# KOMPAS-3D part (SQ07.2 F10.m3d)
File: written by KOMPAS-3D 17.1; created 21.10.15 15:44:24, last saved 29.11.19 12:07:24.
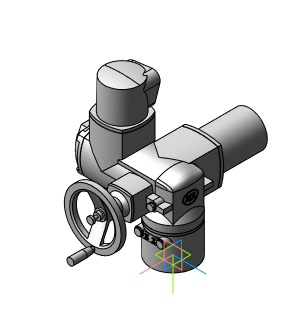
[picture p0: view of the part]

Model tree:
1. Операция без истории:4  (labels: Сталь 20  ГОСТ 1050-88)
